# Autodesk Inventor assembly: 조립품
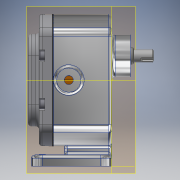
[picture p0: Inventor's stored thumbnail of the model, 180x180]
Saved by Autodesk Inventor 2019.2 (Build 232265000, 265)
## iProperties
Created: 2019-03
Part Number: 조립품
Material: 일반
Document SubType Name: Assembly
Designer: User
Author: User
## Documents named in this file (11)
- C:\Users\User\Desktop\490307V1025\조립품.iam
- C:\Users\User\Desktop\490307V1025\본체.ipt
- C:\Users\User\Desktop\490307V1025\메인축.ipt
- C:\Users\User\Desktop\490307V1025\키 6 x 6 x 18.ipt
- C:\Users\User\Desktop\490307V1025\서브축.ipt
- C:\Users\User\Desktop\490307V1025\베어링부시.ipt
- C:\Users\User\Desktop\490307V1025\커버.ipt
- C:\Users\User\Desktop\490307V1025\스퍼기어.ipt
- C:\Users\User\Desktop\490307V1025\개스킷.ipt
- C:\Users\User\Desktop\490307V1025\오일 실 16 28 7.ipt
- C:\Users\User\Desktop\490307V1025\볼트 M5.ipt
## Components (1 placed, 1 different names)
1. 개스킷:1
